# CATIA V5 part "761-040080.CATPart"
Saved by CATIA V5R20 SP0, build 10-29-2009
Part number: 761-040080
Source: Unknown
Property "ARTICLENO": "761-040080"
Property "BOMINFO": "761-040080"
Property "CODE": "761-040080"
Property "H": "40.000"
Property "L1": "80.000"
Property "L2": "50.000"
Property "LINA": "761-040080"
Property "NB": "761-040080"
Property "NBSYN": "$CODE."
Property "NN": "761"
Property "NT": "VW/AUDI Keys"
Property "P": "4.000"
Property "SUPPLIER": "CF"
Bounding box of the stored display mesh (mm): x -40 to 40, y 0 to 40, z -11 to 11
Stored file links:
  C:\Users\Utente\Desktop\3D files 761\761-040080.CATPart
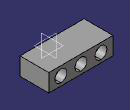
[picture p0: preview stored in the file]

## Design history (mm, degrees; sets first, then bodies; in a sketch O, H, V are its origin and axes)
Body1 "Geometry.1" (main body)
  Solid1 "761-040080.catpart": solid without history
